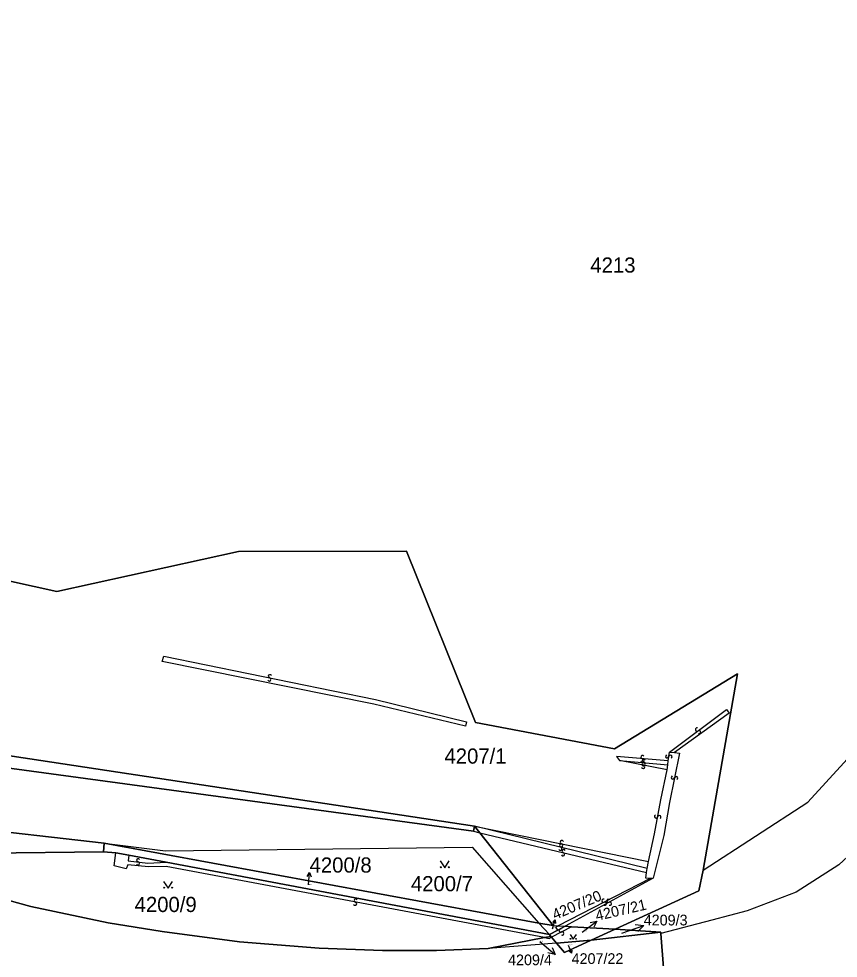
# Model space of a CAD drawing. Extents: x -598233 to -596890, y -1157848 to -1156431.
# Drawn here: x -598127.8 to -598036, y -1157248.6 to -1157143.3 of the extents above; entities that cross this region are included whole.
import ezdxf

# ---------------------------------------------------------------- set-up
doc = ezdxf.new("R2010")
doc.units = 0
for name, color, linetype in [('Level 1', 7, 'Continuous'), ('Level 13', 7, 'Continuous'), ('Level 3', 7, 'Continuous'), ('Level 4', 7, 'Continuous'), ('Level 5', 7, 'Continuous'), ('Level 57', 7, 'Continuous'), ('Level 60', 7, 'Continuous'), ('Vrstva 60', 7, 'Continuous')]:
    doc.layers.add(name, color=color, linetype=linetype)

msp = doc.modelspace()

# ---------------------------------------------------------------- linework, layer by layer
at = {"layer": 'Level 1'}
for points in [[(-598051.08, -1157238.71), (-598039.38, -1157231.1), (-598027.68, -1157218.33), (-598020.26, -1157202.41), (-598013, -1157188.16), (-598007.71, -1157174.7), (-598007.36, -1157164.36), (-598009.87, -1157147.41), (-598011.65, -1157136.39), (-598017.09, -1157116.49), (-598022.5, -1157094.64), (-598023.35, -1157090.35)], [(-598232.89, -1157171.98), (-598210.59, -1157183.62), (-598165.35, -1157198.24), (-598123.48, -1157207.46), (-598103.14, -1157203.01), (-598084.34, -1157202.94), (-598076.6, -1157222.15), (-598061.01, -1157225.1), (-598047.25, -1157216.71), (-598051.08, -1157238.71)], [(-598232.89, -1157190.7), (-598219.56, -1157197.32), (-598179.31, -1157213.48), (-598132.24, -1157225.39), (-598076.7, -1157233.76)], [(-598076.82, -1157234.35), (-598132.41, -1157226.78), (-598179.67, -1157214.91), (-598220.23, -1157198.66), (-598232.89, -1157192.38)], [(-598172.49, -1157226.27), (-598158.37, -1157232.15), (-598145.84, -1157236.77), (-598140.46, -1157238.66), (-598134.18, -1157240.65), (-598126.4, -1157242.77), (-598117.76, -1157244.62), (-598111.68, -1157245.57), (-598103.03, -1157246.73), (-598094.1, -1157247.44), (-598087.01, -1157247.72), (-598080.95, -1157247.72), (-598075.16, -1157247.49)], [(-598118.18, -1157235.69), (-598134.61, -1157233.83), (-598154.86, -1157230.51)], [(-598118.28, -1157236.65), (-598131.33, -1157236.79), (-598154.86, -1157230.51)], [(-598076.7, -1157233.76), (-598076.82, -1157234.35)], [(-598076.1, -1157234.52), (-598076.7, -1157233.76)], [(-598067.89, -1157244.92), (-598076.1, -1157234.52)], [(-598118.18, -1157235.69), (-598118.28, -1157236.65)], [(-598118.28, -1157236.65), (-598116.9, -1157236.78)], [(-598069.5, -1157244.63), (-598118.18, -1157235.69)], [(-598118.18, -1157235.69), (-598111.31, -1157236.53), (-598076.98, -1157236.14), (-598069.5, -1157244.63)], [(-598116.9, -1157236.78), (-598115.41, -1157237.03)], [(-598115.41, -1157237.03), (-598111.23, -1157237.83)], [(-598111.23, -1157237.83), (-598068.29, -1157245.92)], [(-598051.08, -1157238.71), (-598051.58, -1157241.02), (-598060.96, -1157245.33)], [(-598067.89, -1157244.92), (-598069.5, -1157244.63)], [(-598069.5, -1157244.63), (-598068.29, -1157245.92)], [(-598067.89, -1157244.92), (-598067.34, -1157244.95)], [(-598066.54, -1157245), (-598067.39, -1157245.42)], [(-598067.34, -1157244.95), (-598066.54, -1157245)], [(-598065.85, -1157245.04), (-598066.54, -1157245)], [(-598060.96, -1157245.33), (-598065.85, -1157245.04)], [(-598068.17, -1157246.13), (-598068.85, -1157246.26)], [(-598068.29, -1157245.92), (-598067.39, -1157245.42)], [(-598068.17, -1157246.13), (-598068.29, -1157245.92)], [(-598068.17, -1157246.13), (-598068.09, -1157246.23)], [(-598063.64, -1157246.57), (-598060.96, -1157245.33)], [(-598063.64, -1157246.57), (-598055.83, -1157245.64)], [(-598055.83, -1157245.64), (-598060.96, -1157245.33)], [(-598055.83, -1157245.64), (-598055.82, -1157245.82)], [(-598055.82, -1157245.82), (-598055.2, -1157253.99)], [(-598068.85, -1157246.26), (-598075.16, -1157247.49)], [(-598067.52, -1157246.88), (-598075.16, -1157247.49)], [(-598068.09, -1157246.23), (-598067.52, -1157246.88)], [(-598063.64, -1157246.57), (-598067.52, -1157246.88)], [(-598067.52, -1157246.88), (-598066.61, -1157247.93), (-598063.64, -1157246.57)]]:
    msp.add_lwpolyline(points, dxfattribs=at)
at = {"layer": 'Level 13'}
for centre, start, end in [((-598099.7, -1157217.34), 205.5465, 78.1365), ((-598099.62, -1157216.98), 25.7609, 257.8589), ((-598051.78, -1157222.94), 74.2139, 306.3119), ((-598051.56, -1157223.24), 253.9994, 126.5894), ((-598057.88, -1157226.04), 32.2227, 264.8127), ((-598055.12, -1157225.95), 118.7571, 350.8551), ((-598054.76, -1157226.01), 298.5426, 171.1326), ((-598057.92, -1157226.4), 212.4372, 84.5352), ((-598057.82, -1157227.12), 206.3721, 78.4701), ((-598057.74, -1157226.76), 26.1576, 258.7476), ((-598057.73, -1157226.48), 32.3118, 264.4098), ((-598057.77, -1157226.84), 212.0973, 84.6873), ((-598054.48, -1157228.32), 115.5687, 348.1587), ((-598054.12, -1157228.4), 295.7831, 167.8811), ((-598056.36, -1157232.7), 116.6988, 348.7968), ((-598056, -1157232.77), 296.4843, 169.0743), ((-598066.92, -1157235.56), 25.8877, 257.9857), ((-598067.09, -1157236.32), 203.5669, 75.6649), ((-598067, -1157235.96), 23.3524, 255.9424), ((-598067, -1157235.92), 205.6732, 78.2632), ((-598066.72, -1157236.57), 23.9374, 256.0354), ((-598114.38, -1157237.6), 30.8307, 262.9287), ((-598066.8, -1157236.93), 203.7229, 76.3129), ((-598114.42, -1157237.96), 210.6162, 83.2062), ((-598090.02, -1157242.1), 26.5256, 259.1156), ((-598062.27, -1157242.14), 64.4083, 296.9983), ((-598061.71, -1157242.15), 65.8706, 298.4606), ((-598090.09, -1157242.46), 206.74, 78.838), ((-598062.11, -1157242.46), 244.6227, 116.7207), ((-598061.53, -1157242.47), 246.0851, 118.1831), ((-598067.06, -1157245.48), 65.1378, 297.7278), ((-598066.88, -1157245.8), 245.3522, 117.4502)]:
    msp.add_arc(centre, 0.184, start, end, dxfattribs=at)
at = {"layer": 'Level 3'}
for points in [[(-598023.65, -1157087.85), (-598022.34, -1157088.52), (-598021.07, -1157090.38), (-598009.31, -1157138.85), (-598007.57, -1157144.86), (-598006.24, -1157150.59), (-598005.47, -1157155.48), (-598005.19, -1157165.8), (-598005.73, -1157171.88), (-598006.84, -1157177.09), (-598008.31, -1157182.5), (-598025.15, -1157224.52), (-598027.91, -1157229.41), (-598031.36, -1157233.91), (-598035.91, -1157238.1), (-598040.66, -1157241.18), (-598046.15, -1157243.27), (-598050.11, -1157244.33), (-598055.82, -1157245.82)], [(-598111.51, -1157214.72), (-598087.81, -1157219.59), (-598077.59, -1157222.07), (-598077.73, -1157222.56), (-598088, -1157220.12), (-598111.7, -1157215.33), (-598111.51, -1157214.72)], [(-598054.86, -1157225.48), (-598048.48, -1157220.7), (-598048.19, -1157221.11), (-598054.29, -1157225.53)], [(-598055.01, -1157226.47), (-598060.8, -1157225.97), (-598060.46, -1157226.42)], [(-598054.29, -1157225.53), (-598053.74, -1157225.6), (-598054.87, -1157231.11), (-598055.5, -1157234.81), (-598056.7, -1157239.61)], [(-598055.01, -1157226.47), (-598054.86, -1157225.48)], [(-598054.86, -1157225.48), (-598054.29, -1157225.53)], [(-598060.46, -1157226.42), (-598055.04, -1157226.9)], [(-598055.11, -1157227.46), (-598060.46, -1157226.42)], [(-598055.11, -1157227.46), (-598055.04, -1157226.9)], [(-598055.04, -1157226.9), (-598055.01, -1157226.47)], [(-598057.21, -1157237.72), (-598056.54, -1157234.65), (-598055.82, -1157230.83), (-598055.11, -1157227.46)], [(-598076.82, -1157234.35), (-598076.1, -1157234.52)], [(-598076.7, -1157233.76), (-598057.21, -1157237.72)], [(-598057.37, -1157238.51), (-598076.7, -1157233.76)], [(-598076.1, -1157234.52), (-598057.43, -1157238.98)], [(-598068.85, -1157246.26), (-598111.25, -1157238.3), (-598113.21, -1157238.35), (-598115.53, -1157238.12), (-598115.71, -1157238.57), (-598117.08, -1157238.21), (-598116.9, -1157236.78)], [(-598115.41, -1157237.03), (-598115.49, -1157237.66), (-598113.31, -1157237.91), (-598111.23, -1157237.83)], [(-598057.37, -1157238.51), (-598057.21, -1157237.72)], [(-598057.43, -1157238.98), (-598057.37, -1157238.51)], [(-598057.03, -1157239.64), (-598067.34, -1157244.95)], [(-598056.7, -1157239.61), (-598066.54, -1157245)], [(-598057.03, -1157239.64), (-598057.53, -1157239.6), (-598057.43, -1157238.98)], [(-598056.7, -1157239.61), (-598057.03, -1157239.64)], [(-598065.85, -1157245.04), (-598068.09, -1157246.23)], [(-598067.39, -1157245.42), (-598067.59, -1157245.08), (-598067.34, -1157244.95)], [(-598068.85, -1157246.26), (-598068.34, -1157246.36), (-598068.09, -1157246.23)]]:
    msp.add_lwpolyline(points, dxfattribs=at)
at = {"layer": 'Level 5'}
for points in [[(-598080.54, -1157237.68), (-598080.04, -1157238.43), (-598079.54, -1157237.68)], [(-598111.53, -1157239.97), (-598111.03, -1157240.72), (-598110.53, -1157239.97)], [(-598065.98, -1157245.92), (-598065.64, -1157246.43), (-598065.3, -1157245.92)]]:
    msp.add_lwpolyline(points, dxfattribs=at)
for centre, radius in [((-598080.49, -1157238.38), 0.05), ((-598079.59, -1157238.38), 0.05), ((-598111.48, -1157240.67), 0.05), ((-598110.58, -1157240.67), 0.05), ((-598065.95, -1157246.4), 0.034), ((-598065.33, -1157246.4), 0.034)]:
    msp.add_circle(centre, radius, dxfattribs=at)
at = {"layer": 'Level 57'}
for p, q in [((-598095.32, -1157240.36), (-598095.18, -1157238.98)), ((-598067.98, -1157245.27), (-598067.69, -1157244.29)), ((-598064.63, -1157245.66), (-598063.01, -1157244.41)), ((-598060.2, -1157245.78), (-598057.75, -1157244.9)), ((-598069.39, -1157246.71), (-598067.68, -1157248.16)), ((-598066.22, -1157247.13), (-598065.83, -1157248.02))]:
    msp.add_line(p, q, dxfattribs=at)
for points in [[(-598095.46, -1157239.42), (-598095.18, -1157238.98), (-598095, -1157239.46)], [(-598067.95, -1157244.57), (-598067.69, -1157244.29), (-598067.62, -1157244.67)], [(-598063.76, -1157244.56), (-598063.01, -1157244.41), (-598063.34, -1157245.1)], [(-598058.71, -1157244.78), (-598057.75, -1157244.9), (-598058.42, -1157245.6)], [(-598068.01, -1157247.39), (-598067.68, -1157248.16), (-598068.49, -1157247.96)], [(-598065.81, -1157247.66), (-598065.83, -1157248.02), (-598066.11, -1157247.79)]]:
    msp.add_lwpolyline(points, dxfattribs=at)
at = {"layer": 'Level 60'}
msp.add_lwpolyline([(-598024.96, -1157254.01), (-598041.35, -1157257.8), (-598058.57, -1157256.91), (-598059.41, -1157256.94), (-598070.61, -1157258.16), (-598069.25, -1157257.57), (-598068.06, -1157257.15), (-598067.17, -1157256.9), (-598066.35, -1157256.72), (-598055.16, -1157255.86), (-598055.19, -1157254.34), (-598055.2, -1157253.99), (-598055.82, -1157245.82), (-598055.83, -1157245.64), (-598060.96, -1157245.33), (-598051.58, -1157241.02), (-598051.08, -1157238.71), (-598039.38, -1157231.1), (-598027.68, -1157218.33)], dxfattribs=at)
for points in [[(-598172.49, -1157226.27), (-598164.06, -1157229.01), (-598154.86, -1157230.51), (-598131.33, -1157236.79), (-598118.28, -1157236.65), (-598116.9, -1157236.78), (-598115.41, -1157237.03), (-598111.23, -1157237.83), (-598068.29, -1157245.92), (-598068.17, -1157246.13), (-598068.85, -1157246.26), (-598075.16, -1157247.49), (-598080.95, -1157247.72), (-598087.01, -1157247.72), (-598094.1, -1157247.44), (-598103.03, -1157246.73), (-598111.68, -1157245.57), (-598117.76, -1157244.62), (-598126.4, -1157242.77), (-598134.18, -1157240.65), (-598140.46, -1157238.66), (-598145.84, -1157236.77), (-598158.37, -1157232.15)], [(-598134.61, -1157233.83), (-598118.18, -1157235.69), (-598118.28, -1157236.65), (-598131.33, -1157236.79), (-598154.86, -1157230.51)], [(-598118.18, -1157235.69), (-598069.5, -1157244.63), (-598068.29, -1157245.92), (-598111.23, -1157237.83), (-598115.41, -1157237.03), (-598116.9, -1157236.78), (-598118.28, -1157236.65)], [(-598111.31, -1157236.53), (-598076.98, -1157236.14), (-598069.5, -1157244.63), (-598118.18, -1157235.69)], [(-598069.5, -1157244.63), (-598067.89, -1157244.92), (-598067.34, -1157244.95), (-598066.54, -1157245), (-598067.39, -1157245.42), (-598068.29, -1157245.92)], [(-598068.09, -1157246.23), (-598068.17, -1157246.13), (-598068.29, -1157245.92), (-598067.39, -1157245.42), (-598066.54, -1157245), (-598065.85, -1157245.04), (-598060.96, -1157245.33), (-598063.64, -1157246.57), (-598067.52, -1157246.88)], [(-598068.17, -1157246.13), (-598068.09, -1157246.23), (-598067.52, -1157246.88), (-598075.16, -1157247.49), (-598068.85, -1157246.26)], [(-598063.64, -1157246.57), (-598060.96, -1157245.33), (-598055.83, -1157245.64)], [(-598067.52, -1157246.88), (-598063.64, -1157246.57), (-598066.61, -1157247.93)]]:
    msp.add_lwpolyline(points, close=True, dxfattribs=at)
at = {"layer": 'Vrstva 60'}
for points in [[(-598232.89, -1157099.76), (-598232.89, -1157171.98), (-598210.59, -1157183.62), (-598165.35, -1157198.24), (-598123.48, -1157207.46), (-598103.14, -1157203.01), (-598084.34, -1157202.94), (-598076.6, -1157222.15), (-598061.01, -1157225.1), (-598047.25, -1157216.71), (-598051.08, -1157238.71), (-598039.38, -1157231.1), (-598027.68, -1157218.33), (-598020.26, -1157202.41), (-598013, -1157188.16), (-598007.71, -1157174.7), (-598007.36, -1157164.36), (-598009.87, -1157147.41), (-598011.65, -1157136.39)], [(-598055.2, -1157253.99), (-598055.82, -1157245.82), (-598055.83, -1157245.64), (-598063.64, -1157246.57), (-598066.61, -1157247.93), (-598067.52, -1157246.88), (-598075.16, -1157247.49), (-598080.95, -1157247.72), (-598087.01, -1157247.72), (-598094.1, -1157247.44), (-598103.03, -1157246.73), (-598111.68, -1157245.57), (-598117.76, -1157244.62), (-598126.4, -1157242.77), (-598134.18, -1157240.65)]]:
    msp.add_lwpolyline(points, dxfattribs=at)
for points in [[(-598232.89, -1157171.98), (-598232.89, -1157190.7), (-598219.56, -1157197.32), (-598179.31, -1157213.48), (-598132.24, -1157225.39), (-598076.7, -1157233.76), (-598076.1, -1157234.52), (-598067.89, -1157244.92), (-598067.34, -1157244.95), (-598066.54, -1157245), (-598065.85, -1157245.04), (-598060.96, -1157245.33), (-598051.58, -1157241.02), (-598051.08, -1157238.71), (-598047.25, -1157216.71), (-598061.01, -1157225.1), (-598076.6, -1157222.15), (-598084.34, -1157202.94), (-598103.14, -1157203.01), (-598123.48, -1157207.46), (-598165.35, -1157198.24), (-598210.59, -1157183.62)], [(-598232.89, -1157190.7), (-598232.89, -1157192.38), (-598220.23, -1157198.66), (-598179.67, -1157214.91), (-598132.41, -1157226.78), (-598076.82, -1157234.35), (-598076.7, -1157233.76), (-598132.24, -1157225.39), (-598179.31, -1157213.48), (-598219.56, -1157197.32)], [(-598232.89, -1157192.38), (-598232.89, -1157194.81), (-598224.13, -1157199.44), (-598165.41, -1157227.7), (-598154.86, -1157230.51), (-598134.61, -1157233.83), (-598118.18, -1157235.69), (-598111.31, -1157236.53), (-598076.98, -1157236.14), (-598069.5, -1157244.63), (-598067.89, -1157244.92), (-598076.1, -1157234.52), (-598076.7, -1157233.76), (-598076.82, -1157234.35), (-598132.41, -1157226.78), (-598179.67, -1157214.91), (-598220.23, -1157198.66)]]:
    msp.add_lwpolyline(points, close=True, dxfattribs=at)

# ---------------------------------------------------------------- texts
at = {"layer": 'Level 4'}
for s, height, p in [('4200/7', 1.7, (-598083.83, -1157241.07)), ('4200/8', 0.1, (-598095.32, -1157240.36)), ('4200/9', 1.7, (-598114.78, -1157243.4)), ('4209/3', 0.1, (-598060.2, -1157245.78)), ('4209/4', 0.1, (-598069.39, -1157246.71)), ('4207/22', 0.1, (-598066.22, -1157247.13))]:
    msp.add_text(s, height=height, dxfattribs=at).set_placement(p)
for s, rotation, p in [('4207/20', 23, (-598067.98, -1157245.27)), ('4207/21', 13, (-598064.63, -1157245.66))]:
    msp.add_text(s, height=0.1, rotation=rotation, dxfattribs=at).set_placement(p)
at = {"layer": 'Level 57'}
for s, height, p in [('4213', 1.7, (-598063.73, -1157171.74)), ('4207/1', 1.7, (-598080.07, -1157226.77)), ('4200/8', 1.7, (-598095.18, -1157238.98)), ('4209/3', 1.2, (-598057.75, -1157244.9)), ('4209/4', 1.2, (-598072.95, -1157249.36)), ('4207/22', 1.2, (-598065.83, -1157249.22))]:
    msp.add_text(s, height=height, dxfattribs=at).set_placement(p)
for s, rotation, p in [('4207/20', 23, (-598067.69, -1157244.29)), ('4207/21', 13, (-598063.01, -1157244.41))]:
    msp.add_text(s, height=1.2, rotation=rotation, dxfattribs=at).set_placement(p)

doc.saveas('drawing.dxf')
